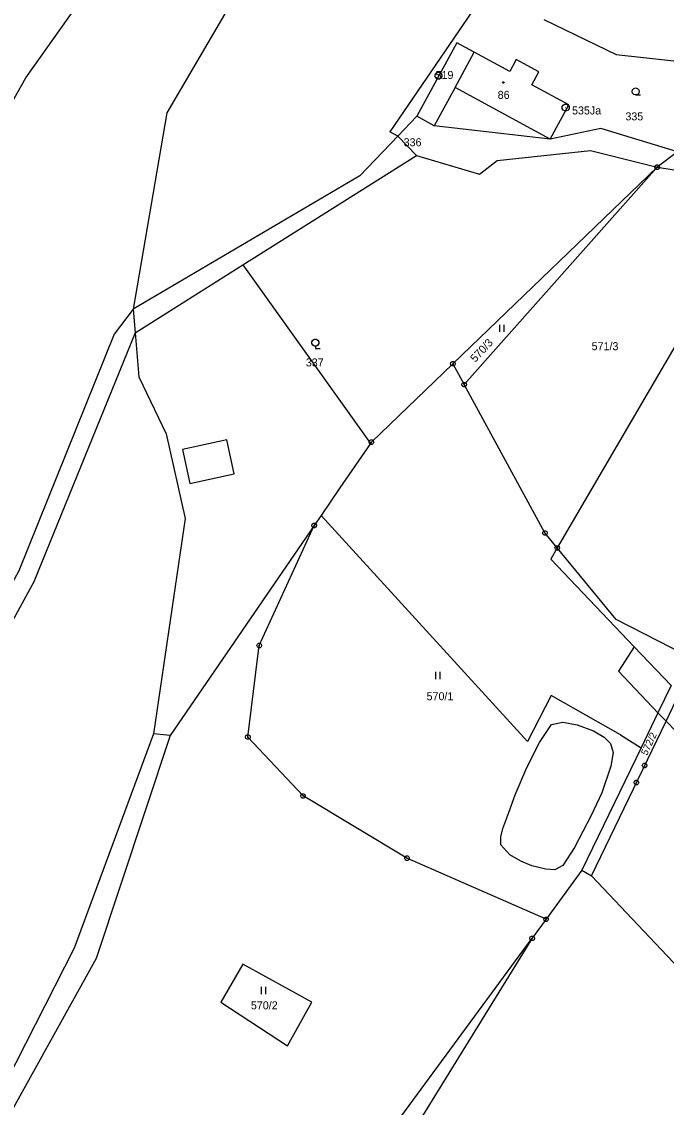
# Model space of a CAD drawing. Extents: x -694465 to -690527, y -983694 to -978978.
# Drawn here: x -692762.8 to -692625.8, y -981851.5 to -981620.9 of the extents above; entities that cross this region are included whole.
import ezdxf

# ---------------------------------------------------------------- set-up
doc = ezdxf.new("R2010")
doc.units = 0
for name, color, linetype in [('Vrstva 1', 7, 'Continuous'), ('Vrstva 17', 7, 'Continuous'), ('Vrstva 18', 7, 'Continuous'), ('Vrstva 19', 7, 'Continuous'), ('Vrstva 24', 7, 'Continuous'), ('Vrstva 25', 7, 'Continuous')]:
    doc.layers.add(name, color=color, linetype=linetype)

msp = doc.modelspace()

# ---------------------------------------------------------------- linework, layer by layer
at = {"layer": 'Vrstva 1'}
for p, q in [((-692650.325, -981764.006), (-692655.329, -981773.775)), ((-692635.598, -981772.381), (-692650.325, -981764.006))]:
    msp.add_line(p, q, dxfattribs=at)
for points in [[(-692761.94, -981632.81), (-692706.43, -981554.45)], [(-692692.31, -981572.45), (-692731.98, -981640.24)], [(-692662.12, -981611.32), (-692684.589, -981644.23)], [(-692651.85, -981620.39), (-692636.5, -981627.81)], [(-692670.39, -981625.36), (-692678.85, -981640.97)], [(-692666.691, -981627.367), (-692670.39, -981625.36)], [(-692670.74, -981634.85), (-692666.691, -981627.367)], [(-692659.13, -981631.47), (-692666.691, -981627.367)], [(-692636.5, -981627.81), (-692609.99, -981630.75)], [(-692657.73, -981628.89), (-692659.13, -981631.47)], [(-692652.92, -981631.5), (-692657.73, -981628.89)], [(-692800, -981700), (-692761.94, -981632.81)], [(-692654.42, -981634.26), (-692652.92, -981631.5)], [(-692670.74, -981634.85), (-692675.15, -981642.97)], [(-692650.5, -981645.83), (-692670.74, -981634.85)], [(-692646.54, -981638.54), (-692654.42, -981634.26)], [(-692650.5, -981645.83), (-692646.54, -981638.54)], [(-692731.98, -981640.24), (-692739.14, -981681.97)], [(-692678.85, -981640.97), (-692682.872, -981645.154)], [(-692675.15, -981642.97), (-692678.85, -981640.97)], [(-692682.872, -981645.154), (-692684.589, -981644.23)], [(-692650.5, -981645.83), (-692675.15, -981642.97)], [(-692639.79, -981643.53), (-692650.5, -981645.83)], [(-692623.46, -981648.54), (-692639.79, -981643.53)], [(-692682.872, -981645.154), (-692690.98, -981653.59)], [(-692678.96, -981649.31), (-692682.872, -981645.154)], [(-692661.78, -981650.38), (-692641.97, -981648.26)], [(-692641.97, -981648.26), (-692627.78, -981651.76)], [(-692623.46, -981648.54), (-692627.78, -981651.76)], [(-692715.865, -981672.558), (-692678.96, -981649.31)], [(-692678.96, -981649.31), (-692665.52, -981653.24)], [(-692665.52, -981653.24), (-692661.78, -981650.38)], [(-692690.98, -981653.59), (-692739.14, -981681.97)], [(-692627.78, -981651.76), (-692671.21, -981693.54)], [(-692668.8, -981697.97), (-692627.78, -981651.76)], [(-692627.78, -981651.76), (-692603.92, -981655.47)], [(-692603.92, -981655.47), (-692649.01, -981732.68)], [(-692738.71, -981686.95), (-692715.865, -981672.558)], [(-692715.865, -981672.558), (-692688.706, -981710.461)], [(-692739.14, -981681.97), (-692743.195, -981687.274), (-692763.408, -981737.542), (-692797.483, -981800.811), (-692807.707, -981815.69)], [(-692739.14, -981681.97), (-692738.71, -981686.95)], [(-692738.71, -981686.95), (-692760.232, -981739.853), (-692794.018, -981801.678), (-692804.616, -981818.408)], [(-692738.71, -981686.95), (-692737.92, -981696.33)], [(-692671.21, -981693.54), (-692688.52, -981710.19)], [(-692671.21, -981693.54), (-692668.8, -981697.97)], [(-692737.92, -981696.33), (-692732.13, -981708.44)], [(-692651.64, -981729.5), (-692668.8, -981697.97)], [(-692732.13, -981708.44), (-692728.12, -981726.44)], [(-692728.648, -981711.753), (-692727.101, -981718.973), (-692717.675, -981716.953), (-692719.222, -981709.733), (-692728.648, -981711.753)], [(-692688.706, -981710.461), (-692695.189, -981719.916)], [(-692688.52, -981710.19), (-692688.706, -981710.461)], [(-692695.189, -981719.916), (-692699.21, -981725.78)], [(-692728.12, -981726.44), (-692734.8, -981772.2)], [(-692699.21, -981725.78), (-692700.67, -981727.91)], [(-692655.329, -981773.775), (-692699.21, -981725.78)], [(-692700.67, -981727.91), (-692731.26, -981772.55)], [(-692712.33, -981753.41), (-692700.67, -981727.91)], [(-692649.01, -981732.68), (-692651.64, -981729.5)], [(-692649.01, -981732.68), (-692650.411, -981735.091), (-692632.679, -981753.678)], [(-692636.5, -981747.89), (-692649.01, -981732.68)], [(-692621.72, -981755.44), (-692636.5, -981747.89)], [(-692714.77, -981772.86), (-692712.33, -981753.41)], [(-692632.679, -981753.678), (-692636.029, -981758.848), (-692627.627, -981767.695)], [(-692632.679, -981753.678), (-692624.834, -981761.901)], [(-692624.834, -981761.901), (-692627.627, -981767.695)], [(-692625.904, -981769.474), (-692623.118, -981763.7)], [(-692627.627, -981767.695), (-692631.207, -981775.121)], [(-692627.627, -981767.695), (-692625.904, -981769.474)], [(-692657.991, -981785.164), (-692655.515, -981779.307), (-692652.813, -981774.013), (-692650.223, -981770.183), (-692647.859, -981769.733), (-692644.819, -981770.296), (-692641.329, -981771.535), (-692639.078, -981772.886), (-692637.727, -981774.238), (-692637.164, -981776.153), (-692637.614, -981779.081), (-692639.528, -981784.713), (-692641.78, -981789.556)], [(-692641.76, -981802.34), (-692625.904, -981769.474)], [(-692625.904, -981769.474), (-692601.738, -981794.428)], [(-692734.8, -981772.2), (-692751.66, -981817.75)], [(-692731.26, -981772.55), (-692747, -981819.92)], [(-692731.26, -981772.55), (-692734.8, -981772.2)], [(-692703.04, -981785.37), (-692714.77, -981772.86)], [(-692635.598, -981772.381), (-692631.207, -981775.121)], [(-692631.207, -981775.121), (-692643.76, -981801.16)], [(-692641.78, -981789.556), (-692645.382, -981796.314), (-692647.859, -981800.144), (-692649.548, -981801.045), (-692651.462, -981800.933), (-692654.389, -981800.257), (-692656.753, -981799.243), (-692659.117, -981797.891), (-692661.031, -981795.751), (-692661.031, -981794.062), (-692660.581, -981792.26), (-692659.342, -981788.881), (-692657.991, -981785.164)], [(-692680.95, -981798.6), (-692703.04, -981785.37)], [(-692651.39, -981811.58), (-692680.95, -981798.6)], [(-692643.76, -981801.16), (-692651.39, -981811.58)], [(-692643.76, -981801.16), (-692641.76, -981802.34)], [(-692616.99, -981828.48), (-692641.76, -981802.34)], [(-692651.39, -981811.58), (-692654.35, -981815.63)], [(-692701.52, -981879.79), (-692654.35, -981815.63)], [(-692654.35, -981815.63), (-692695.36, -981882.04)], [(-692751.66, -981817.75), (-692768.35, -981850.3)], [(-692747, -981819.92), (-692765.33, -981853)], [(-692701.14, -981829.216), (-692715.867, -981821.127), (-692720.487, -981829.216), (-692706.338, -981838.461)], [(-692706.338, -981838.461), (-692701.14, -981829.216)]]:
    msp.add_lwpolyline(points, dxfattribs=at)
at = {"layer": 'Vrstva 24'}
for points in [[(-692674.066, -981631.596), (-692673.73, -981631.79), (-692673.536, -981632.126), (-692673.536, -981632.514), (-692673.73, -981632.85), (-692674.066, -981633.044), (-692674.454, -981633.044), (-692674.79, -981632.85), (-692674.984, -981632.514), (-692674.984, -981632.126), (-692674.79, -981631.79), (-692674.454, -981631.596)], [(-692647.046, -981638.376), (-692646.71, -981638.57), (-692646.516, -981638.906), (-692646.516, -981639.294), (-692646.71, -981639.63), (-692647.046, -981639.824), (-692647.434, -981639.824), (-692647.77, -981639.63), (-692647.964, -981639.294), (-692647.964, -981638.906), (-692647.77, -981638.57), (-692647.434, -981638.376)], [(-692627.626, -981651.284), (-692627.376, -981651.466), (-692627.28, -981651.76), (-692627.376, -981652.054), (-692627.626, -981652.236), (-692627.934, -981652.236), (-692628.184, -981652.054), (-692628.28, -981651.76), (-692628.184, -981651.466), (-692627.934, -981651.284)], [(-692627.626, -981651.284), (-692627.376, -981651.466), (-692627.28, -981651.76), (-692627.376, -981652.054), (-692627.626, -981652.236), (-692627.934, -981652.236), (-692628.184, -981652.054), (-692628.28, -981651.76), (-692628.184, -981651.466), (-692627.934, -981651.284)], [(-692671.056, -981693.064), (-692670.806, -981693.246), (-692670.71, -981693.54), (-692670.806, -981693.834), (-692671.056, -981694.016), (-692671.364, -981694.016), (-692671.614, -981693.834), (-692671.71, -981693.54), (-692671.614, -981693.246), (-692671.364, -981693.064)], [(-692671.056, -981693.064), (-692670.806, -981693.246), (-692670.71, -981693.54), (-692670.806, -981693.834), (-692671.056, -981694.016), (-692671.364, -981694.016), (-692671.614, -981693.834), (-692671.71, -981693.54), (-692671.614, -981693.246), (-692671.364, -981693.064)], [(-692668.646, -981697.494), (-692668.396, -981697.676), (-692668.3, -981697.97), (-692668.396, -981698.264), (-692668.646, -981698.446), (-692668.954, -981698.446), (-692669.204, -981698.264), (-692669.3, -981697.97), (-692669.204, -981697.676), (-692668.954, -981697.494)], [(-692688.366, -981709.714), (-692688.116, -981709.896), (-692688.02, -981710.19), (-692688.116, -981710.484), (-692688.366, -981710.666), (-692688.674, -981710.666), (-692688.924, -981710.484), (-692689.02, -981710.19), (-692688.924, -981709.896), (-692688.674, -981709.714)], [(-692688.366, -981709.714), (-692688.116, -981709.896), (-692688.02, -981710.19), (-692688.116, -981710.484), (-692688.366, -981710.666), (-692688.674, -981710.666), (-692688.924, -981710.484), (-692689.02, -981710.19), (-692688.924, -981709.896), (-692688.674, -981709.714)], [(-692700.516, -981727.434), (-692700.266, -981727.616), (-692700.17, -981727.91), (-692700.266, -981728.204), (-692700.516, -981728.386), (-692700.824, -981728.386), (-692701.074, -981728.204), (-692701.17, -981727.91), (-692701.074, -981727.616), (-692700.824, -981727.434)], [(-692700.516, -981727.434), (-692700.266, -981727.616), (-692700.17, -981727.91), (-692700.266, -981728.204), (-692700.516, -981728.386), (-692700.824, -981728.386), (-692701.074, -981728.204), (-692701.17, -981727.91), (-692701.074, -981727.616), (-692700.824, -981727.434)], [(-692651.486, -981729.024), (-692651.236, -981729.206), (-692651.14, -981729.5), (-692651.236, -981729.794), (-692651.486, -981729.976), (-692651.794, -981729.976), (-692652.044, -981729.794), (-692652.14, -981729.5), (-692652.044, -981729.206), (-692651.794, -981729.024)], [(-692648.856, -981732.204), (-692648.606, -981732.386), (-692648.51, -981732.68), (-692648.606, -981732.974), (-692648.856, -981733.156), (-692649.164, -981733.156), (-692649.414, -981732.974), (-692649.51, -981732.68), (-692649.414, -981732.386), (-692649.164, -981732.204)], [(-692712.176, -981752.934), (-692711.926, -981753.116), (-692711.83, -981753.41), (-692711.926, -981753.704), (-692712.176, -981753.886), (-692712.484, -981753.886), (-692712.734, -981753.704), (-692712.83, -981753.41), (-692712.734, -981753.116), (-692712.484, -981752.934)], [(-692714.616, -981772.384), (-692714.366, -981772.566), (-692714.27, -981772.86), (-692714.366, -981773.154), (-692714.616, -981773.336), (-692714.924, -981773.336), (-692715.174, -981773.154), (-692715.27, -981772.86), (-692715.174, -981772.566), (-692714.924, -981772.384)], [(-692630.306, -981778.444), (-692630.056, -981778.626), (-692629.96, -981778.92), (-692630.056, -981779.214), (-692630.306, -981779.396), (-692630.614, -981779.396), (-692630.864, -981779.214), (-692630.96, -981778.92), (-692630.864, -981778.626), (-692630.614, -981778.444)], [(-692632.046, -981782.054), (-692631.796, -981782.236), (-692631.7, -981782.53), (-692631.796, -981782.824), (-692632.046, -981783.006), (-692632.354, -981783.006), (-692632.604, -981782.824), (-692632.7, -981782.53), (-692632.604, -981782.236), (-692632.354, -981782.054)], [(-692702.886, -981784.894), (-692702.636, -981785.076), (-692702.54, -981785.37), (-692702.636, -981785.664), (-692702.886, -981785.846), (-692703.194, -981785.846), (-692703.444, -981785.664), (-692703.54, -981785.37), (-692703.444, -981785.076), (-692703.194, -981784.894)], [(-692680.796, -981798.124), (-692680.546, -981798.306), (-692680.45, -981798.6), (-692680.546, -981798.894), (-692680.796, -981799.076), (-692681.104, -981799.076), (-692681.354, -981798.894), (-692681.45, -981798.6), (-692681.354, -981798.306), (-692681.104, -981798.124)], [(-692651.236, -981811.104), (-692650.986, -981811.286), (-692650.89, -981811.58), (-692650.986, -981811.874), (-692651.236, -981812.056), (-692651.544, -981812.056), (-692651.794, -981811.874), (-692651.89, -981811.58), (-692651.794, -981811.286), (-692651.544, -981811.104)], [(-692654.196, -981815.154), (-692653.946, -981815.336), (-692653.85, -981815.63), (-692653.946, -981815.924), (-692654.196, -981816.106), (-692654.504, -981816.106), (-692654.754, -981815.924), (-692654.85, -981815.63), (-692654.754, -981815.336), (-692654.504, -981815.154)]]:
    msp.add_lwpolyline(points, close=True, dxfattribs=at)
for points in [[(-692674.31, -981632.32), (-692674.21, -981632.32)], [(-692647.29, -981639.1), (-692647.19, -981639.1)], [(-692627.899, -981651.76), (-692627.66, -981651.76)], [(-692627.899, -981651.76), (-692627.66, -981651.76)], [(-692671.329, -981693.54), (-692671.09, -981693.54)], [(-692671.329, -981693.54), (-692671.09, -981693.54)], [(-692668.919, -981697.97), (-692668.68, -981697.97)], [(-692688.639, -981710.19), (-692688.4, -981710.19)], [(-692688.639, -981710.19), (-692688.4, -981710.19)], [(-692700.789, -981727.91), (-692700.55, -981727.91)], [(-692700.789, -981727.91), (-692700.55, -981727.91)], [(-692651.759, -981729.5), (-692651.52, -981729.5)], [(-692649.129, -981732.68), (-692648.89, -981732.68)], [(-692712.449, -981753.41), (-692712.21, -981753.41)], [(-692714.889, -981772.86), (-692714.65, -981772.86)], [(-692630.579, -981778.92), (-692630.34, -981778.92)], [(-692632.319, -981782.53), (-692632.08, -981782.53)], [(-692703.159, -981785.37), (-692702.92, -981785.37)], [(-692681.069, -981798.6), (-692680.83, -981798.6)], [(-692651.509, -981811.58), (-692651.27, -981811.58)], [(-692654.469, -981815.63), (-692654.23, -981815.63)]]:
    msp.add_lwpolyline(points, dxfattribs=at)
at = {"layer": 'Vrstva 25'}
msp.add_lwpolyline([(-692660.403, -981633.628), (-692660.315, -981633.78), (-692660.403, -981633.932), (-692660.577, -981633.932), (-692660.665, -981633.78), (-692660.577, -981633.628)], close=True, dxfattribs=at)
for points in [[(-692632.36, -981636.43), (-692632.735, -981636.329), (-692633.009, -981636.055), (-692633.11, -981635.68), (-692633.009, -981635.305), (-692632.735, -981635.031), (-692632.36, -981634.93), (-692631.985, -981635.031), (-692631.711, -981635.305), (-692631.61, -981635.68), (-692631.711, -981636.055), (-692631.985, -981636.329), (-692632.36, -981636.43), (-692631.36, -981636.431)], [(-692661.32, -981685.26), (-692661.32, -981686.76)], [(-692660.32, -981686.76), (-692660.32, -981685.26)], [(-692700.409, -981689.794), (-692700.604, -981689.794), (-692700.939, -981689.6), (-692701.134, -981689.264), (-692701.134, -981688.877), (-692700.941, -981688.54), (-692700.604, -981688.346), (-692700.217, -981688.346), (-692699.88, -981688.54), (-692699.686, -981688.875), (-692699.686, -981689.265), (-692699.879, -981689.6), (-692700.217, -981689.794), (-692700.409, -981689.794), (-692700.41, -981690.32), (-692699.409, -981690.318)], [(-692674.88, -981759.04), (-692674.88, -981760.54)], [(-692673.88, -981760.54), (-692673.88, -981759.04)], [(-692711.93, -981825.97), (-692711.93, -981827.47)], [(-692710.93, -981827.47), (-692710.93, -981825.97)]]:
    msp.add_lwpolyline(points, dxfattribs=at)

# ---------------------------------------------------------------- texts
at = {"layer": 'Vrstva 17'}
for s, p in [('519', (-692674.877, -981633.04)), ('535Ja', (-692645.873, -981640.57))]:
    msp.add_text(s, height=1.7, dxfattribs=at).set_placement(p)
at = {"layer": 'Vrstva 18'}
for s, p in [('335', (-692634.535, -981641.83)), ('336', (-692681.658, -981647.33)), ('571/3', (-692641.713, -981690.66)), ('337', (-692702.448, -981694.11)), ('570/1', (-692676.783, -981765.04)), ('570/2', (-692714.123, -981830.72))]:
    msp.add_text(s, height=1.7, dxfattribs=at).set_placement(p)
for s, height, rotation, p in [('570/3', 1.7, 46.81065, (-692666.438, -981693.347)), ('572/2', 1.51, 64.80153, (-692629.957, -981776.893))]:
    msp.add_text(s, height=height, rotation=rotation, dxfattribs=at).set_placement(p)
at = {"layer": 'Vrstva 19'}
msp.add_text('86', height=1.7, dxfattribs=at).set_placement((-692661.672, -981637.26))

doc.saveas('drawing.dxf')
